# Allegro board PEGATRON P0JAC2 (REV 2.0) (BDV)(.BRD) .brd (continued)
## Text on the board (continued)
User.28: FIGURE | SIZE | 4.0 | TOLERANCE | +2.0/-2.0 | DRILL CHART: TOP to L2-SIG (1 to 2) | ALL UNITS ARE IN MILS | PLATED | ROTATION | - | QTY | 5799 | TOTAL HOLES:
User.34: FIGURE | SIZE | 4.0 | TOLERANCE | +2.0/-2.0 | DRILL CHART: L2-SIG to L3-GND (2 to 3) | ALL UNITS ARE IN MILS | PLATED | ROTATION | - | QTY | 6133 | TOTAL HOLES:
User.36: FIGURE | SIZE | 4.0 | TOLERANCE | +2.0/-2.0 | DRILL CHART: L7-SIG to BOTTOM (7 to 8) | ALL UNITS ARE IN MILS | PLATED | ROTATION | - | QTY | 6276 | TOTAL HOLES:
